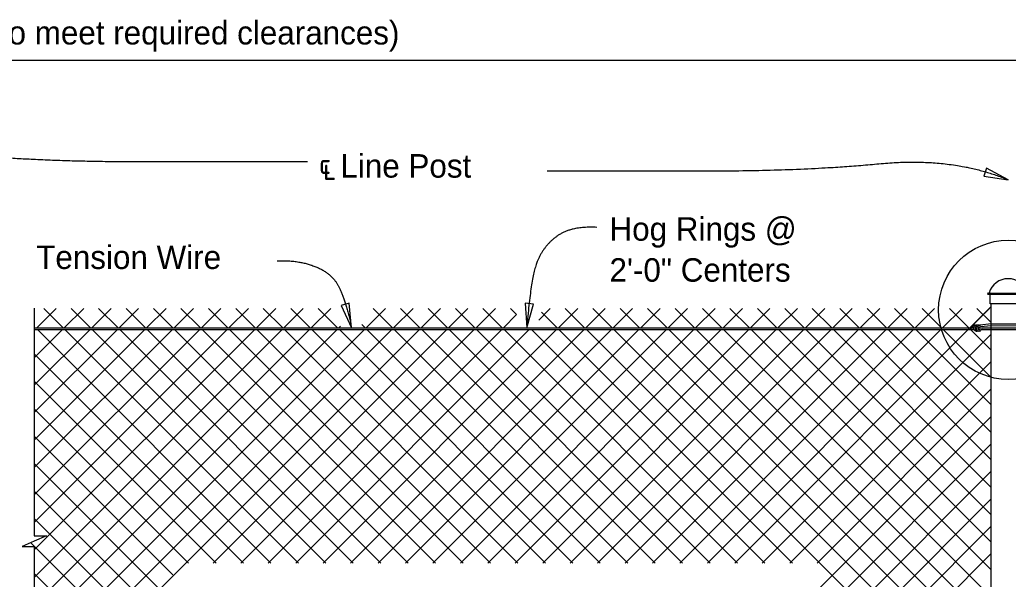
# Model space of a CAD drawing. Extents: x 0.2 to 40.8, y 0.5 to 25.7.
# Drawn here: x 16.13 to 24.62, y 20.9 to 25.7 of the extents above; entities that cross this region are included whole.
import ezdxf

# ---------------------------------------------------------------- set-up
doc = ezdxf.new("R2010")
doc.units = 0
for name, color, linetype in [('Dimension', 7, 'Continuous'), ('Miscellaneous', 7, 'Continuous'), ('SteelMisc', 7, 'Continuous'), ('SteelMisc_h', 7, 'Continuous'), ('TextStructures', 7, 'Continuous')]:
    doc.layers.add(name, color=color, linetype=linetype)

msp = doc.modelspace()

# ---------------------------------------------------------------- linework, layer by layer
at = {"layer": 'Dimension'}
for points in [[(13.615, 25.3556), (15.0787, 25.3556), (15.0787, 25.4589), (15.1237, 25.3556), (15.1687, 25.2523), (15.1687, 25.3556), (28.4596, 25.3556)], [(16.252, 23.2265), (16.252, 21.2702), (16.3553, 21.2702), (16.252, 21.2252), (16.1487, 21.1802), (16.252, 21.1802), (16.252, 20.2867)]]:
    msp.add_lwpolyline(points, dxfattribs=at)
for points in [[(24.6151, 24.3284), (24.4287, 24.4277), (24.4064, 24.3608)], [(18.9764, 23.0579), (18.9562, 23.2681), (18.8881, 23.2497)], [(20.4816, 23.0579), (20.5377, 23.2615), (20.4675, 23.2686)]]:
    msp.add_lwpolyline(points, close=True, dxfattribs=at)
msp.add_circle((24.615, 23.212), 0.5976, dxfattribs=at)
for points in [[(18.5966, 24.4827), (17.7933, 24.4827), (16.4039, 24.4827), (15.2225, 24.5773), (14.615, 24.6814)], [(20.6562, 24.4046), (21.1029, 24.4046), (22.8703, 24.4046), (24.1369, 24.5276), (24.615, 24.3283)], [(21.0813, 23.9198), (20.8634, 23.9322), (20.6196, 23.7577), (20.5135, 23.4738), (20.4817, 23.0578)], [(18.338, 23.6332), (18.5184, 23.6403), (18.8013, 23.5305), (18.9216, 23.311), (18.9764, 23.0578)]]:
    msp.add_open_spline(points, degree=2, dxfattribs=at)
at = {"layer": 'Miscellaneous'}
for p, q in [((16.2736, 23.0578), (16.4402, 23.2245)), ((16.3328, 23.2245), (16.4994, 23.0578)), ((16.5093, 23.0578), (16.6759, 23.2245)), ((16.5685, 23.2245), (16.7352, 23.0578)), ((16.745, 23.0578), (16.9116, 23.2245)), ((16.8042, 23.2245), (16.9709, 23.0578)), ((16.9807, 23.0578), (17.1473, 23.2245)), ((17.0399, 23.2245), (17.2066, 23.0578)), ((17.2164, 23.0578), (17.383, 23.2245)), ((17.2756, 23.2245), (17.4423, 23.0578)), ((17.4521, 23.0578), (17.6187, 23.2245)), ((17.5113, 23.2245), (17.678, 23.0578)), ((17.6878, 23.0578), (17.8544, 23.2245)), ((17.747, 23.2245), (17.9137, 23.0578)), ((17.9235, 23.0578), (18.0901, 23.2245)), ((17.9827, 23.2245), (18.1494, 23.0578)), ((18.1592, 23.0578), (18.3258, 23.2245)), ((18.2184, 23.2245), (18.3851, 23.0578)), ((18.3949, 23.0578), (18.5615, 23.2245)), ((18.4541, 23.2245), (18.6208, 23.0578)), ((18.6306, 23.0578), (18.7972, 23.2245)), ((18.6898, 23.2245), (18.8565, 23.0578)), ((19.102, 23.0578), (19.2687, 23.2245)), ((19.1612, 23.2245), (19.3279, 23.0578)), ((19.3377, 23.0578), (19.5044, 23.2245)), ((19.3969, 23.2245), (19.5636, 23.0578)), ((19.5734, 23.0578), (19.7401, 23.2245)), ((19.6326, 23.2245), (19.7993, 23.0578)), ((19.8091, 23.0578), (19.9758, 23.2245)), ((19.8683, 23.2245), (20.035, 23.0578)), ((20.0448, 23.0578), (20.2115, 23.2245)), ((20.104, 23.2245), (20.2707, 23.0578)), ((20.3397, 23.2245), (20.3934, 23.1708)), ((20.5829, 23.1245), (20.6829, 23.2245)), ((20.6086, 23.1914), (20.7421, 23.0578)), ((20.7519, 23.0578), (20.9186, 23.2245)), ((20.8111, 23.2245), (20.9778, 23.0578)), ((20.9876, 23.0578), (21.1543, 23.2245)), ((21.0468, 23.2245), (21.2135, 23.0578)), ((21.2233, 23.0578), (21.39, 23.2245)), ((21.2825, 23.2245), (21.4492, 23.0578)), ((21.459, 23.0578), (21.6257, 23.2245)), ((21.5182, 23.2245), (21.6849, 23.0578)), ((21.6947, 23.0578), (21.8614, 23.2245)), ((21.7539, 23.2245), (21.9206, 23.0578)), ((21.9304, 23.0578), (22.0971, 23.2245)), ((21.9896, 23.2245), (22.1563, 23.0578)), ((22.1661, 23.0578), (22.3328, 23.2245)), ((22.2253, 23.2245), (22.392, 23.0578)), ((22.2674, 21.0378), (24.4692, 23.2396)), ((22.4018, 23.0578), (22.5685, 23.2245)), ((22.461, 23.2245), (22.6277, 23.0578)), ((22.6375, 23.0578), (22.8042, 23.2245)), ((22.6967, 23.2245), (22.8634, 23.0578)), ((22.8732, 23.0578), (23.0399, 23.2245)), ((22.9324, 23.2245), (23.0991, 23.0578)), ((23.1089, 23.0578), (23.2756, 23.2245)), ((23.1681, 23.2245), (23.3348, 23.0578)), ((23.3446, 23.0578), (23.5113, 23.2245)), ((23.4038, 23.2245), (23.5705, 23.0578)), ((23.5803, 23.0578), (23.747, 23.2245)), ((23.6396, 23.2245), (23.8062, 23.0578)), ((23.816, 23.0578), (23.9827, 23.2245)), ((23.8753, 23.2245), (24.0419, 23.0578)), ((24.0517, 23.0578), (24.2184, 23.2245)), ((24.111, 23.2245), (24.2776, 23.0578)), ((24.2874, 23.0578), (24.4541, 23.2245)), ((24.3467, 23.2245), (24.4692, 23.1019)), ((20.2805, 23.0578), (20.3934, 23.1708)), ((16.252, 19.7364), (19.5586, 23.0431)), ((16.252, 20.2078), (19.0872, 23.0431)), ((16.252, 21.1506), (18.1444, 23.0431)), ((16.252, 20.6792), (18.6158, 23.0431)), ((16.252, 19.9721), (19.3229, 23.0431)), ((16.252, 20.4435), (18.8515, 23.0431)), ((16.252, 20.9149), (18.3801, 23.0431)), ((16.252, 21.3863), (17.9087, 23.0431)), ((16.252, 21.622), (17.673, 23.0431)), ((16.252, 22.0934), (17.2016, 23.0431)), ((16.252, 21.8577), (17.4373, 23.0431)), ((16.252, 22.5648), (16.7302, 23.0431)), ((16.252, 23.0363), (16.2588, 23.0431)), ((16.252, 22.3291), (16.9659, 23.0431)), ((16.252, 22.8005), (16.4945, 23.0431)), ((16.2785, 23.0431), (18.2838, 21.0378)), ((16.5142, 23.0431), (18.5195, 21.0378)), ((16.7499, 23.0431), (18.7552, 21.0378)), ((16.9856, 23.0431), (18.9909, 21.0378)), ((17.2213, 23.0431), (19.2266, 21.0378)), ((17.457, 23.0431), (19.4623, 21.0378)), ((17.6927, 23.0431), (19.698, 21.0378)), ((17.7891, 21.0378), (19.7943, 23.0431)), ((17.9284, 23.0431), (19.9337, 21.0378)), ((18.0248, 21.0378), (20.03, 23.0431)), ((18.1641, 23.0431), (20.1694, 21.0378)), ((18.2605, 21.0378), (20.2657, 23.0431)), ((18.3998, 23.0431), (20.4051, 21.0378)), ((18.4962, 21.0378), (20.5014, 23.0431)), ((18.6355, 23.0431), (20.6408, 21.0378)), ((18.7319, 21.0378), (20.7372, 23.0431)), ((18.8663, 23.0578), (18.8813, 23.0728)), ((18.8712, 23.0431), (20.8765, 21.0378)), ((18.9676, 21.0378), (20.9729, 23.0431)), ((19.065, 23.085), (19.0922, 23.0578)), ((19.1069, 23.0431), (21.1122, 21.0378)), ((19.2033, 21.0378), (21.2086, 23.0431)), ((19.3426, 23.0431), (21.3479, 21.0378)), ((19.439, 21.0378), (21.4443, 23.0431)), ((19.5783, 23.0431), (21.5836, 21.0378)), ((19.6747, 21.0378), (21.68, 23.0431)), ((19.814, 23.0431), (21.8193, 21.0378)), ((19.9104, 21.0378), (21.9157, 23.0431)), ((20.0497, 23.0431), (22.055, 21.0378)), ((20.1461, 21.0378), (22.1514, 23.0431)), ((20.2854, 23.0431), (22.2907, 21.0378)), ((20.3818, 21.0378), (22.3871, 23.0431)), ((20.5211, 23.0431), (22.5264, 21.0378)), ((20.6175, 21.0378), (22.6228, 23.0431)), ((20.7568, 23.0431), (22.7621, 21.0378)), ((20.8532, 21.0378), (22.8585, 23.0431)), ((20.9925, 23.0431), (24.4692, 19.5664)), ((21.0889, 21.0378), (23.0942, 23.0431)), ((21.2282, 23.0431), (24.4692, 19.8021)), ((21.3246, 21.0378), (23.3299, 23.0431)), ((21.4639, 23.0431), (24.4692, 20.0378)), ((21.5603, 21.0378), (23.5656, 23.0431)), ((21.6996, 23.0431), (24.4692, 20.2735)), ((21.796, 21.0378), (23.8013, 23.0431)), ((21.9353, 23.0431), (24.4692, 20.5092)), ((22.0317, 21.0378), (24.037, 23.0431)), ((22.1711, 23.0431), (24.4692, 20.7449)), ((22.4068, 23.0431), (24.4692, 20.9806)), ((22.5031, 21.0378), (24.4692, 23.0039)), ((22.6425, 23.0431), (24.4692, 21.2163)), ((22.8782, 23.0431), (24.4692, 21.452)), ((23.1139, 23.0431), (24.4692, 21.6877)), ((23.3496, 23.0431), (24.4692, 21.9234)), ((23.5853, 23.0431), (24.4692, 22.1591)), ((23.821, 23.0431), (24.4692, 22.3948)), ((24.0567, 23.0431), (24.4692, 22.6305)), ((24.2924, 23.0431), (24.4692, 22.8662)), ((16.252, 22.8339), (18.0481, 21.0378)), ((22.7388, 21.0378), (24.4692, 22.7682)), ((16.252, 22.5982), (17.8124, 21.0378)), ((22.9745, 21.0378), (24.4692, 22.5325)), ((16.252, 22.3625), (17.5767, 21.0378)), ((22.9985, 20.8261), (24.4692, 22.2968)), ((16.252, 22.1268), (17.4417, 20.9371)), ((22.9985, 20.5904), (24.4692, 22.0611)), ((16.252, 21.8911), (17.4417, 20.7014)), ((22.9985, 20.3547), (24.4692, 21.8254)), ((16.252, 21.6554), (17.4417, 20.4657)), ((22.9985, 20.119), (24.4692, 21.5897)), ((16.252, 21.4197), (17.4417, 20.23)), ((21.9677, 18.8525), (24.4692, 21.354)), ((16.2232, 21.2127), (17.4417, 19.9943)), ((22.2034, 18.8525), (24.4692, 21.1183)), ((16.252, 20.9483), (19.7943, 17.4059))]:
    msp.add_line(p, q, dxfattribs=at)
at = {"layer": 'SteelMisc'}
for p, q in [((24.4427, 23.3564), (24.7873, 23.3564)), ((24.7873, 23.3442), (24.4427, 23.3442)), ((24.461, 23.2645), (24.461, 23.3442)), ((24.7691, 23.2645), (24.461, 23.2645)), ((24.4692, 16.8894), (24.4692, 23.2644)), ((24.4692, 23.0904), (24.3743, 23.0793)), ((24.4692, 23.0904), (24.7604, 23.0921)), ((16.252, 23.0578), (24.2941, 23.0578)), ((16.252, 23.0431), (24.3207, 23.0431)), ((24.304, 23.0578), (24.3172, 23.0578)), ((24.4692, 23.0759), (24.3766, 23.0664)), ((24.3856, 23.0431), (24.4692, 23.0431)), ((24.387, 23.0578), (24.4692, 23.0578)), ((24.4692, 23.0759), (24.7604, 23.0776))]:
    msp.add_line(p, q, dxfattribs=at)
msp.add_arc((24.4429, 23.3502), 0.00613, 91.1647, 268.8353, dxfattribs=at)
for centre, major_axis, ratio, start_param, end_param in [((24.6157, 23.3154), (0.1711, 0), 0.957868, 0.252602, 2.888574), ((24.3283, 23.0436), (0.0373, 0), 0.957868, 1.486836, 3.108042), ((24.3494, 23.0039), (-0.0724, 0), 0.957868, 5.162149, 5.652106), ((24.3419, 23.0555), (-0.0249, 0), 0.957868, 6.009018, 7.089857), ((24.3408, 23.058), (0.023, 0), 0.957868, 1.29026, 2.970541), ((24.3433, 23.0515), (0.0231, 0), 0.957868, 3.779554, 4.879821), ((24.3595, 23.0527), (0.0295, 0), 0.957868, 1.220941, 4.039556), ((24.373, 23.0544), (-0.0303, -0.0108), 0.724765, 4.35367, 6.324556), ((24.3494, 23.0458), (0.0206, -0.0021), 0.798607, 4.32653, 5.220153), ((24.3629, 23.0458), (0.0206, -0.0021), 0.798607, 3.333154, 5.220153), ((24.3697, 23.0504), (-0.0139, 0), 0.957868, 5.22362, 6.905413), ((24.364, 23.048), (-0.00795, 0), 0.957868, 6.140374, 9.314262), ((24.3781, 23.0415), (-0.0259, 0), 0.957868, 4.777514, 5.62749), ((24.3624, 23.0538), (0.0119, 0), 0.957868, 5.725876, 7.416677), ((24.3555, 23.0646), (0.0391, 0), 0.957868, 5.082588, 5.41974), ((24.3624, 23.0538), (0.0119, 0), 0.957868, 5.639684, 5.723117), ((24.3626, 23.0525), (0.0251, 0), 0.957868, 5.531357, 6.227833), ((24.3626, 23.0525), (0.0251, 0), 0.957868, 0.407687, 0.609214)]:
    msp.add_ellipse(centre, major_axis=major_axis, ratio=ratio, start_param=start_param, end_param=end_param, dxfattribs=at)
at = {"layer": 'SteelMisc_h'}
for p, q in [((24.4692, 23.0578), (24.7609, 23.0578)), ((24.4692, 23.0431), (24.7609, 23.0431))]:
    msp.add_line(p, q, dxfattribs=at)

# ---------------------------------------------------------------- texts
at = {"layer": 'Dimension'}
for s, p in [('Hog Rings @ ', (21.1911, 23.8055)), ('2\'-0" Centers', (21.1911, 23.4535))]:
    msp.add_text(s, height=0.2016, dxfattribs=at).set_placement(p)
at = {"layer": 'TextStructures'}
for s, p in [('Equal Spaces @ 10\'-0" Max. (Posts may be shifted minimally to meet required clearances)', (8.5826, 25.4902)), ('℄ Line Post', (18.6958, 24.347)), ('Tension Wire', (16.268, 23.5627))]:
    msp.add_text(s, height=0.2016, dxfattribs=at).set_placement(p)

doc.saveas('drawing.dxf')
